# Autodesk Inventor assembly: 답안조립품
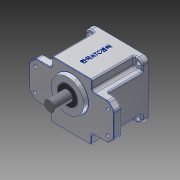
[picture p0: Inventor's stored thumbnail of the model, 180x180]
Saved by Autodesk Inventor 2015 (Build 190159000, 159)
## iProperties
Created: 2016-02
Part Number: 답안조립품
Document SubType Name: Assembly
Designer: Administrator
Author: Administrator
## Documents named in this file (10)
- C:\Users\Administrator\Desktop\460209V1003\답안조립품.iam
- C:\Users\Administrator\Desktop\460209V1003\본체.ipt
- C:\Users\Administrator\Desktop\460209V1003\커버.ipt
- C:\Users\Administrator\Desktop\460209V1003\볼트 M4 x 10.ipt
- C:\Users\Administrator\Desktop\460209V1003\오일실 8 22 7.ipt
- C:\Users\Administrator\Desktop\460209V1003\베어링 608.ipt
- C:\Users\Administrator\Desktop\460209V1003\서브축.ipt
- C:\Users\Administrator\Desktop\460209V1003\메인축.ipt
- C:\Users\Administrator\Desktop\460209V1003\베어링 6003.ipt
- C:\Users\Administrator\Desktop\460209V1003\오일실 17 32 8.ipt
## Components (2 placed, 1 different names)
1. ISO 4762 M4 x 10:1 — Insert:1
2. ISO 4762 M4 x 10:2 — Insert:2
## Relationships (2: Insert 2)
- Insert:1: ISO 4762 M4 x 10:1
- Insert:2: ISO 4762 M4 x 10:2
